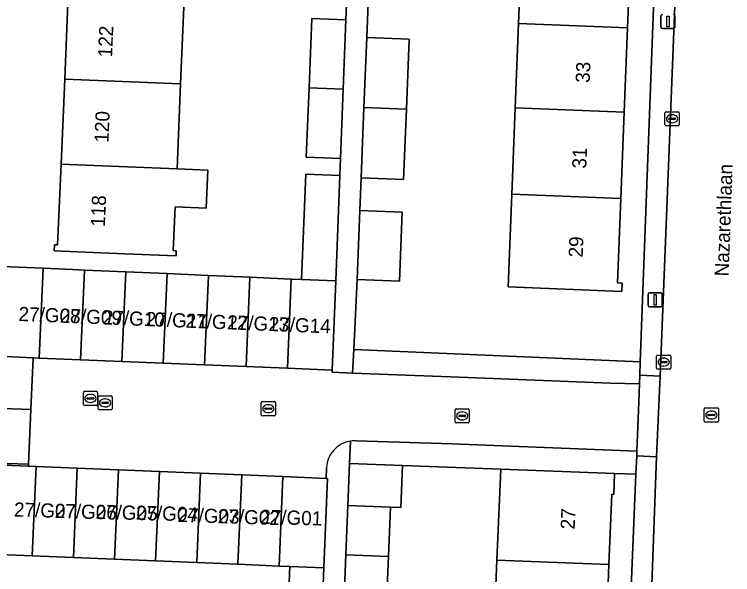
# Model space of a CAD drawing. Extents: x 161354 to 162026, y 386504 to 387460.
# Drawn here: x 161454.5 to 161505.3, y 387313.9 to 387353.5 of the extents above; entities that cross this region are included whole.
import ezdxf

# ---------------------------------------------------------------- set-up
doc = ezdxf.new("R2010")
doc.units = 0
for name, color, linetype in [('IMGEO_Erf', 7, 'Continuous'), ('IMGEO_Kolk', 7, 'Continuous'), ('IMGEO_Lichtmast', 7, 'Continuous'), ('IMGEO_Openbare_ruimte_label', 7, 'Continuous'), ('IMGEO_Pand', 7, 'Continuous'), ('IMGEO_Pand_nummerreeks', 7, 'Continuous'), ('IMGEO_Rijbaan_lokaal_open', 7, 'Continuous'), ('IMGEO_Rioolput', 7, 'Continuous'), ('IMGEO_Voetpad_open', 7, 'Continuous')]:
    doc.layers.add(name, color=color, linetype=linetype)

msp = doc.modelspace()

# ---------------------------------------------------------------- linework, layer by layer
at = {"layer": 'IMGEO_Erf'}
for points in [[(161479.478, 387354.331), (161479.382, 387351.907), (161482.38, 387351.788), (161482.183, 387346.822), (161481.986, 387341.858), (161478.988, 387341.977), (161478.897, 387339.661), (161481.894, 387339.542), (161481.701, 387334.668), (161478.704, 387334.787), (161478.46, 387329.827), (161498.714, 387328.954), (161500, 387363.41)], [(161498.072, 387358.868), (161497.821, 387352.583), (161497.583, 387346.613), (161497.339, 387340.512), (161497.101, 387334.546), (161497.442, 387334.532), (161497.419, 387333.947), (161489.37, 387334.268), (161489.632, 387340.821), (161489.876, 387346.922), (161490.114, 387352.891), (161490.365, 387359.176)], [(161453.573, 387335.71), (161456.498, 387335.582), (161458.569, 387335.492), (161459.424, 387335.455), (161462.349, 387335.327), (161465.274, 387335.199), (161468.2, 387335.072), (161471.125, 387334.944), (161474.051, 387334.817), (161474.773, 387334.785), (161475.065, 387342.244), (161477.483, 387342.146), (161477.53, 387343.346), (161475.112, 387343.441), (161475.304, 387348.337), (161475.496, 387353.233), (161477.915, 387353.138), (161478.001, 387355.333)], [(161466.483, 387354.617), (161466.227, 387348.614), (161465.972, 387342.612), (161468.145, 387342.524), (161468.03, 387339.827), (161465.832, 387339.921), (161465.7, 387336.824), (161465.916, 387336.815), (161465.901, 387336.451), (161462.284, 387336.605), (161457.288, 387336.817), (161457.306, 387337.241), (161457.531, 387337.231), (161457.774, 387342.945), (161458.029, 387348.947), (161458.285, 387354.95)], [(161451.637, 387325.727), (161455.634, 387325.588), (161455.79, 387329.244), (161453.296, 387329.353)], [(161453.093, 387321.69), (161455.463, 387321.592), (161455.468, 387321.718), (161451.502, 387321.855)], [(161488.347, 387309.015), (161488.591, 387314.933), (161488.868, 387321.367), (161481.919, 387321.628), (161481.801, 387318.661), (161481.051, 387318.691), (161480.912, 387315.2), (161480.717, 387310.314)], [(161497.171, 387291.265), (161498.419, 387321.01), (161496.91, 387321.066), (161496.854, 387319.589), (161496.703, 387319.595), (161496.51, 387314.625), (161496.28, 387308.706)], [(161473.671, 387307.859), (161473.94, 387314.493), (161473.186, 387314.524), (161470.277, 387314.645), (161467.367, 387314.765), (161464.458, 387314.885), (161461.549, 387315.006), (161458.64, 387315.126), (161455.731, 387315.247), (161449.389, 387315.509)]]:
    msp.add_lwpolyline(points, dxfattribs=at)
at = {"layer": 'IMGEO_Kolk'}
for p, q in [((161500.469, 387345.724), (161500.469, 387346.576)), ((161500.544, 387346.65), (161501.396, 387346.65)), ((161500.957, 387346.43), (161500.982, 387346.43)), ((161501.47, 387346.576), (161501.47, 387345.724)), ((161500.728, 387346.144), (161500.728, 387346.156)), ((161501.166, 387346.107), (161500.768, 387346.107)), ((161500.771, 387346.193), (161501.169, 387346.193)), ((161500.98, 387345.87), (161500.955, 387345.87)), ((161501.212, 387346.156), (161501.212, 387346.144)), ((161501.396, 387345.65), (161500.544, 387345.65)), ((161499.876, 387328.516), (161499.876, 387329.368)), ((161499.951, 387329.442), (161500.803, 387329.442)), ((161500.364, 387329.222), (161500.389, 387329.222)), ((161500.877, 387329.368), (161500.877, 387328.516)), ((161500.135, 387328.936), (161500.135, 387328.948)), ((161500.573, 387328.899), (161500.175, 387328.899)), ((161500.178, 387328.985), (161500.576, 387328.985)), ((161500.387, 387328.662), (161500.362, 387328.662)), ((161500.619, 387328.948), (161500.619, 387328.936)), ((161500.803, 387328.442), (161499.951, 387328.442)), ((161460.459, 387326.562), (161461.311, 387326.562)), ((161460.384, 387325.636), (161460.384, 387326.488)), ((161460.643, 387326.056), (161460.643, 387326.068)), ((161460.686, 387326.105), (161461.084, 387326.105)), ((161460.872, 387326.342), (161460.897, 387326.342)), ((161461.127, 387326.068), (161461.127, 387326.056)), ((161461.385, 387326.488), (161461.385, 387325.636)), ((161471.927, 387325.223), (161471.927, 387326.075)), ((161472.002, 387326.149), (161472.854, 387326.149)), ((161472.928, 387326.075), (161472.928, 387325.223)), ((161461.311, 387325.562), (161460.459, 387325.562)), ((161461.081, 387326.019), (161460.683, 387326.019)), ((161460.895, 387325.782), (161460.87, 387325.782)), ((161472.186, 387325.643), (161472.186, 387325.655)), ((161472.624, 387325.606), (161472.226, 387325.606)), ((161472.229, 387325.692), (161472.627, 387325.692)), ((161472.415, 387325.929), (161472.44, 387325.929)), ((161472.67, 387325.655), (161472.67, 387325.643)), ((161485.629, 387324.715), (161485.629, 387325.567)), ((161485.704, 387325.641), (161486.556, 387325.641)), ((161486.63, 387325.567), (161486.63, 387324.715)), ((161472.854, 387325.149), (161472.002, 387325.149)), ((161472.438, 387325.369), (161472.413, 387325.369)), ((161485.888, 387325.135), (161485.888, 387325.147)), ((161486.326, 387325.098), (161485.928, 387325.098)), ((161485.931, 387325.184), (161486.329, 387325.184)), ((161486.117, 387325.421), (161486.142, 387325.421)), ((161486.372, 387325.147), (161486.372, 387325.135)), ((161486.556, 387324.641), (161485.704, 387324.641)), ((161486.14, 387324.861), (161486.115, 387324.861))]:
    msp.add_line(p, q, dxfattribs=at)
for points in [[(161500.469, 387345.724), (161500.469, 387346.576)], [(161500.544, 387346.65), (161501.396, 387346.65)], [(161501.47, 387346.576), (161501.47, 387345.724)], [(161501.396, 387345.65), (161500.544, 387345.65)], [(161499.876, 387328.516), (161499.876, 387329.368)], [(161499.951, 387329.442), (161500.803, 387329.442)], [(161500.877, 387329.368), (161500.877, 387328.516)], [(161500.803, 387328.442), (161499.951, 387328.442)], [(161460.459, 387326.562), (161461.311, 387326.562)], [(161460.384, 387325.636), (161460.384, 387326.488)], [(161461.385, 387326.488), (161461.385, 387325.636)], [(161471.927, 387325.223), (161471.927, 387326.075)], [(161472.002, 387326.149), (161472.854, 387326.149)], [(161472.928, 387326.075), (161472.928, 387325.223)], [(161461.311, 387325.562), (161460.459, 387325.562)], [(161485.629, 387324.715), (161485.629, 387325.567)], [(161485.704, 387325.641), (161486.556, 387325.641)], [(161486.63, 387325.567), (161486.63, 387324.715)], [(161472.854, 387325.149), (161472.002, 387325.149)], [(161486.556, 387324.641), (161485.704, 387324.641)]]:
    msp.add_lwpolyline(points, dxfattribs=at)
for centre, radius, start, end in [((161500.546, 387346.574), 0.0765, 91.552, 178.448), ((161500.546, 387346.574), 0.0765, 91.552, 178.448), ((161501.394, 387346.574), 0.0765, 1.552, 88.448), ((161501.394, 387346.574), 0.0765, 1.552, 88.448), ((161500.768, 387346.153), 0.0403, 85.8775, 175.7526), ((161500.765, 387346.143), 0.0366, 178.938, 274.7102), ((161501.169, 387346.15), 0.043, 264.8664, 352.4533), ((161501.173, 387346.155), 0.0386, 1.7309, 96.639), ((161500.546, 387345.726), 0.0765, 181.552, 268.448), ((161500.546, 387345.726), 0.0765, 181.552, 268.448), ((161501.394, 387345.726), 0.0765, 271.552, 358.448), ((161501.394, 387345.726), 0.0765, 271.552, 358.448), ((161499.953, 387329.366), 0.0765, 91.552, 178.448), ((161499.953, 387329.366), 0.0765, 91.552, 178.448), ((161500.801, 387329.366), 0.0765, 1.552, 88.448), ((161500.801, 387329.366), 0.0765, 1.552, 88.448), ((161500.175, 387328.945), 0.0403, 85.8775, 175.7526), ((161500.172, 387328.935), 0.0366, 178.938, 274.7102), ((161500.576, 387328.942), 0.043, 264.8664, 352.4533), ((161500.58, 387328.947), 0.0386, 1.7309, 96.639), ((161499.953, 387328.518), 0.0765, 181.552, 268.448), ((161499.953, 387328.518), 0.0765, 181.552, 268.448), ((161500.801, 387328.518), 0.0765, 271.552, 358.448), ((161500.801, 387328.518), 0.0765, 271.552, 358.448), ((161460.461, 387326.486), 0.0765, 91.552, 178.448), ((161460.461, 387326.486), 0.0765, 91.552, 178.448), ((161461.309, 387326.486), 0.0765, 1.552, 88.448), ((161461.309, 387326.486), 0.0765, 1.552, 88.448), ((161460.683, 387326.065), 0.0403, 85.8775, 175.7526), ((161460.68, 387326.055), 0.0366, 178.938, 274.7102), ((161461.084, 387326.062), 0.043, 264.8664, 352.4533), ((161461.088, 387326.067), 0.0386, 1.7309, 96.639), ((161472.004, 387326.073), 0.0765, 91.552, 178.448), ((161472.004, 387326.073), 0.0765, 91.552, 178.448), ((161472.852, 387326.073), 0.0765, 1.552, 88.448), ((161472.852, 387326.073), 0.0765, 1.552, 88.448), ((161460.461, 387325.638), 0.0765, 181.552, 268.448), ((161460.461, 387325.638), 0.0765, 181.552, 268.448), ((161461.309, 387325.638), 0.0765, 271.552, 358.448), ((161461.309, 387325.638), 0.0765, 271.552, 358.448), ((161472.226, 387325.652), 0.0403, 85.8775, 175.7526), ((161472.223, 387325.642), 0.0366, 178.938, 274.7102), ((161472.627, 387325.649), 0.043, 264.8664, 352.4533), ((161472.631, 387325.654), 0.0386, 1.7309, 96.639), ((161485.706, 387325.565), 0.0765, 91.552, 178.448), ((161485.706, 387325.565), 0.0765, 91.552, 178.448), ((161486.554, 387325.565), 0.0765, 1.552, 88.448), ((161486.554, 387325.565), 0.0765, 1.552, 88.448), ((161472.004, 387325.225), 0.0765, 181.552, 268.448), ((161472.004, 387325.225), 0.0765, 181.552, 268.448), ((161472.852, 387325.225), 0.0765, 271.552, 358.448), ((161472.852, 387325.225), 0.0765, 271.552, 358.448), ((161485.928, 387325.144), 0.0403, 85.8775, 175.7526), ((161485.925, 387325.134), 0.0366, 178.938, 274.7102), ((161486.329, 387325.141), 0.043, 264.8664, 352.4533), ((161486.333, 387325.146), 0.0386, 1.7309, 96.639), ((161485.706, 387324.717), 0.0765, 181.552, 268.448), ((161485.706, 387324.717), 0.0765, 181.552, 268.448), ((161486.554, 387324.717), 0.0765, 271.552, 358.448), ((161486.554, 387324.717), 0.0765, 271.552, 358.448)]:
    msp.add_arc(centre, radius, start, end, dxfattribs=at)
for centre, major_axis, ratio, start_param, end_param in [((161500.956, 387346.15), (-0.387, 0.002), 0.722429, 4.712389, 7.853982), ((161500.981, 387346.15), (-0.39, 0.002), 0.717154, 1.570796, 4.712389), ((161500.363, 387328.942), (-0.387, 0.002), 0.722429, 4.712389, 7.853982), ((161500.388, 387328.942), (-0.39, 0.002), 0.717154, 1.570796, 4.712389), ((161460.871, 387326.062), (-0.387, 0.002), 0.722429, 4.712389, 7.853982), ((161460.896, 387326.062), (-0.39, 0.002), 0.717154, 1.570796, 4.712389), ((161472.414, 387325.649), (-0.387, 0.002), 0.722429, 4.712389, 7.853982), ((161472.439, 387325.649), (-0.39, 0.002), 0.717154, 1.570796, 4.712389), ((161486.116, 387325.141), (-0.387, 0.002), 0.722429, 4.712389, 7.853982), ((161486.141, 387325.141), (-0.39, 0.002), 0.717154, 1.570796, 4.712389)]:
    msp.add_ellipse(centre, major_axis=major_axis, ratio=ratio, start_param=start_param, end_param=end_param, dxfattribs=at)
at = {"layer": 'IMGEO_Lichtmast'}
for p, q in [((161500.184, 387352.633), (161500.184, 387353.433)), ((161500.184, 387353.433), (161500.184, 387352.633)), ((161501.174, 387353.433), (161501.174, 387352.633)), ((161501.174, 387352.633), (161501.174, 387353.433)), ((161501.074, 387352.533), (161500.284, 387352.533)), ((161500.284, 387352.533), (161501.074, 387352.533)), ((161499.285, 387332.942), (161499.285, 387333.742)), ((161499.285, 387333.742), (161499.285, 387332.942)), ((161499.385, 387333.842), (161500.175, 387333.842)), ((161500.175, 387333.842), (161499.385, 387333.842)), ((161500.275, 387333.742), (161500.275, 387332.942)), ((161500.275, 387332.942), (161500.275, 387333.742)), ((161500.175, 387332.842), (161499.385, 387332.842)), ((161499.385, 387332.842), (161500.175, 387332.842))]:
    msp.add_line(p, q, dxfattribs=at)
for points in [[(161500.604, 387353.408), (161500.754, 387353.408), (161500.754, 387352.658), (161500.604, 387352.658), (161500.604, 387353.408)], [(161499.705, 387333.717), (161499.855, 387333.717), (161499.855, 387332.967), (161499.705, 387332.967), (161499.705, 387333.717)]]:
    msp.add_lwpolyline(points, dxfattribs=at)
for centre, start, end in [((161500.284, 387353.433), 90, 180), ((161500.284, 387353.433), 90, 180), ((161501.074, 387353.433), 0, 90), ((161501.074, 387353.433), 360, 90), ((161500.284, 387352.633), 180, 270), ((161500.284, 387352.633), 180, 270), ((161501.074, 387352.633), 270, 0), ((161501.074, 387352.633), 270, 0), ((161499.385, 387333.742), 90, 180), ((161499.385, 387333.742), 90, 180), ((161500.175, 387333.742), 0, 90), ((161500.175, 387333.742), 360, 90), ((161499.385, 387332.942), 180, 270), ((161499.385, 387332.942), 180, 270), ((161500.175, 387332.942), 270, 0), ((161500.175, 387332.942), 270, 0)]:
    msp.add_arc(centre, 0.1, start, end, dxfattribs=at)
at = {"layer": 'IMGEO_Pand'}
for points in [[(161490.365, 387359.176), (161490.114, 387352.891), (161497.821, 387352.583), (161498.072, 387358.868)], [(161458.285, 387354.95), (161458.029, 387348.947), (161466.227, 387348.614), (161466.483, 387354.617)], [(161477.915, 387353.138), (161475.496, 387353.233), (161475.304, 387348.337), (161477.723, 387348.242)], [(161497.583, 387346.613), (161497.821, 387352.583), (161490.114, 387352.891), (161489.876, 387346.922)], [(161479.382, 387351.907), (161479.185, 387346.941), (161482.183, 387346.822), (161482.38, 387351.788)], [(161466.227, 387348.614), (161458.029, 387348.947), (161457.774, 387342.945), (161465.972, 387342.612)], [(161477.723, 387348.242), (161475.304, 387348.337), (161475.112, 387343.441), (161477.53, 387343.346)], [(161482.183, 387346.822), (161479.185, 387346.941), (161478.988, 387341.977), (161481.986, 387341.858)], [(161497.339, 387340.512), (161497.583, 387346.613), (161489.876, 387346.922), (161489.632, 387340.821)], [(161465.832, 387339.921), (161468.03, 387339.827), (161468.145, 387342.524), (161465.972, 387342.612), (161457.774, 387342.945), (161457.531, 387337.231), (161457.306, 387337.241), (161457.288, 387336.817), (161462.284, 387336.605), (161465.901, 387336.451), (161465.916, 387336.815), (161465.7, 387336.824)], [(161477.483, 387342.146), (161475.065, 387342.244), (161474.773, 387334.785), (161477.19, 387334.68)], [(161489.632, 387340.821), (161489.37, 387334.268), (161497.419, 387333.947), (161497.442, 387334.532), (161497.101, 387334.546), (161497.339, 387340.512)], [(161478.897, 387339.661), (161478.704, 387334.787), (161481.701, 387334.668), (161481.894, 387339.542)], [(161456.221, 387329.225), (161456.498, 387335.582), (161453.573, 387335.71), (161453.296, 387329.353), (161455.79, 387329.244)], [(161459.424, 387335.455), (161458.569, 387335.492), (161456.498, 387335.582), (161456.221, 387329.225), (161459.146, 387329.105)], [(161462.349, 387335.327), (161459.424, 387335.455), (161459.146, 387329.105), (161462.073, 387328.986)], [(161465.274, 387335.199), (161462.349, 387335.327), (161462.073, 387328.986), (161464.998, 387328.866)], [(161468.2, 387335.072), (161465.274, 387335.199), (161464.998, 387328.866), (161467.924, 387328.747)], [(161471.125, 387334.944), (161468.2, 387335.072), (161467.924, 387328.747), (161470.85, 387328.627)], [(161474.051, 387334.817), (161471.125, 387334.944), (161470.85, 387328.627), (161473.775, 387328.507)], [(161477.19, 387334.68), (161474.773, 387334.785), (161474.051, 387334.817), (161473.775, 387328.507), (161476.943, 387328.378)], [(161455.634, 387325.588), (161451.637, 387325.727), (161451.502, 387321.855), (161455.468, 387321.718)], [(161456.002, 387321.57), (161455.463, 387321.592), (161453.093, 387321.69), (161453.006, 387319.672), (161449.575, 387319.82), (161449.389, 387315.509), (161455.731, 387315.247)], [(161458.912, 387321.449), (161456.002, 387321.57), (161455.731, 387315.247), (161458.64, 387315.126)], [(161481.919, 387321.628), (161478.172, 387321.783), (161478.054, 387318.81), (161481.051, 387318.691), (161481.801, 387318.661)], [(161461.821, 387321.329), (161458.912, 387321.449), (161458.64, 387315.126), (161461.549, 387315.006)], [(161464.73, 387321.208), (161461.821, 387321.329), (161461.549, 387315.006), (161464.458, 387314.885)], [(161467.639, 387321.088), (161464.73, 387321.208), (161464.458, 387314.885), (161467.367, 387314.765)], [(161470.548, 387320.968), (161467.639, 387321.088), (161467.367, 387314.765), (161470.277, 387314.645)], [(161496.703, 387319.595), (161496.854, 387319.589), (161496.91, 387321.066), (161488.868, 387321.367), (161488.591, 387314.933), (161496.51, 387314.625)], [(161473.458, 387320.847), (161470.548, 387320.968), (161470.277, 387314.645), (161473.186, 387314.524)], [(161476.51, 387320.721), (161473.458, 387320.847), (161473.186, 387314.524), (161473.94, 387314.493), (161476.358, 387314.393), (161476.614, 387320.716)], [(161481.051, 387318.691), (161478.054, 387318.81), (161477.915, 387315.319), (161480.912, 387315.2)], [(161480.912, 387315.2), (161477.915, 387315.319), (161477.72, 387310.433), (161480.717, 387310.314)], [(161488.591, 387314.933), (161488.347, 387309.015), (161496.28, 387308.706), (161496.51, 387314.625)], [(161476.358, 387314.393), (161473.94, 387314.493), (161473.671, 387307.859), (161476.089, 387307.761)]]:
    msp.add_lwpolyline(points, close=True, dxfattribs=at)
at = {"layer": 'IMGEO_Rijbaan_lokaal_open'}
for points in [[(161502.454, 387386.874), (161500.117, 387327.957), (161499.877, 387322.239), (161499.07, 387300.302)], [(161498.568, 387324.92), (161498.656, 387327.384), (161498.657, 387327.408), (161496.596, 387327.461), (161486.557, 387327.847), (161478.378, 387328.168), (161476.937, 387328.224), (161476.943, 387328.378), (161473.775, 387328.507), (161470.85, 387328.627), (161467.924, 387328.747), (161464.998, 387328.866), (161462.073, 387328.986), (161459.146, 387329.105), (161456.221, 387329.225), (161455.79, 387329.244), (161455.634, 387325.588), (161455.468, 387321.718), (161455.463, 387321.592), (161456.002, 387321.57), (161458.912, 387321.449), (161461.821, 387321.329), (161464.73, 387321.208), (161467.639, 387321.088), (161470.548, 387320.968), (161473.458, 387320.847), (161476.51, 387320.721), (161476.54, 387321.475)], [(161478.661, 387323.383), (161485.419, 387323.168), (161498.487, 387322.651), (161498.568, 387324.92)]]:
    msp.add_lwpolyline(points, dxfattribs=at)
for centre, radius, start, end in [((161478.542, 387321.382), 2.005, 98.8236, 177.343), ((161478.545, 387321.312), 2.075, 86.7883, 98.5876)]:
    msp.add_arc(centre, radius, start, end, dxfattribs=at)
at = {"layer": 'IMGEO_Rioolput'}
for p, q in [((161459.347, 387325.951), (161459.347, 387326.803)), ((161459.422, 387326.877), (161460.274, 387326.877)), ((161459.835, 387326.657), (161459.86, 387326.657)), ((161460.348, 387326.803), (161460.348, 387325.951)), ((161459.606, 387326.371), (161459.606, 387326.383)), ((161460.044, 387326.334), (161459.646, 387326.334)), ((161459.649, 387326.42), (161460.047, 387326.42)), ((161459.858, 387326.097), (161459.833, 387326.097)), ((161460.09, 387326.383), (161460.09, 387326.371)), ((161460.274, 387325.877), (161459.422, 387325.877)), ((161503.246, 387324.776), (161503.246, 387325.628)), ((161503.321, 387325.702), (161504.173, 387325.702)), ((161504.247, 387325.628), (161504.247, 387324.776)), ((161503.505, 387325.196), (161503.505, 387325.208)), ((161503.943, 387325.159), (161503.545, 387325.159)), ((161503.548, 387325.245), (161503.946, 387325.245)), ((161503.734, 387325.482), (161503.759, 387325.482)), ((161503.989, 387325.208), (161503.989, 387325.196)), ((161504.173, 387324.702), (161503.321, 387324.702)), ((161503.757, 387324.922), (161503.732, 387324.922))]:
    msp.add_line(p, q, dxfattribs=at)
for points in [[(161459.347, 387325.951), (161459.347, 387326.803)], [(161459.422, 387326.877), (161460.274, 387326.877)], [(161460.348, 387326.803), (161460.348, 387325.951)], [(161460.274, 387325.877), (161459.422, 387325.877)], [(161503.246, 387324.776), (161503.246, 387325.628)], [(161503.321, 387325.702), (161504.173, 387325.702)], [(161504.247, 387325.628), (161504.247, 387324.776)], [(161504.173, 387324.702), (161503.321, 387324.702)]]:
    msp.add_lwpolyline(points, dxfattribs=at)
for centre, radius, start, end in [((161459.424, 387326.801), 0.0765, 91.552, 178.448), ((161459.424, 387326.801), 0.0765, 91.552, 178.448), ((161460.272, 387326.801), 0.0765, 1.552, 88.448), ((161460.272, 387326.801), 0.0765, 1.552, 88.448), ((161459.646, 387326.38), 0.0403, 85.8775, 175.7526), ((161459.643, 387326.37), 0.0366, 178.938, 274.7102), ((161460.047, 387326.377), 0.043, 264.8664, 352.4533), ((161460.051, 387326.382), 0.0386, 1.7309, 96.639), ((161459.424, 387325.953), 0.0765, 181.552, 268.448), ((161459.424, 387325.953), 0.0765, 181.552, 268.448), ((161460.272, 387325.953), 0.0765, 271.552, 358.448), ((161460.272, 387325.953), 0.0765, 271.552, 358.448), ((161503.323, 387325.626), 0.0765, 91.552, 178.448), ((161503.323, 387325.626), 0.0765, 91.552, 178.448), ((161504.171, 387325.626), 0.0765, 1.552, 88.448), ((161504.171, 387325.626), 0.0765, 1.552, 88.448), ((161503.545, 387325.205), 0.0403, 85.8775, 175.7526), ((161503.542, 387325.195), 0.0366, 178.938, 274.7102), ((161503.946, 387325.202), 0.043, 264.8664, 352.4533), ((161503.95, 387325.207), 0.0386, 1.7309, 96.639), ((161503.323, 387324.778), 0.0765, 181.552, 268.448), ((161503.323, 387324.778), 0.0765, 181.552, 268.448), ((161504.171, 387324.778), 0.0765, 271.552, 358.448), ((161504.171, 387324.778), 0.0765, 271.552, 358.448)]:
    msp.add_arc(centre, radius, start, end, dxfattribs=at)
for centre, major_axis, ratio, start_param, end_param in [((161459.834, 387326.377), (-0.387, 0.002), 0.722429, 4.712389, 7.853982), ((161459.859, 387326.377), (-0.39, 0.002), 0.717154, 1.570796, 4.712389), ((161503.733, 387325.202), (-0.387, 0.002), 0.722429, 4.712389, 7.853982), ((161503.758, 387325.202), (-0.39, 0.002), 0.717154, 1.570796, 4.712389)]:
    msp.add_ellipse(centre, major_axis=major_axis, ratio=ratio, start_param=start_param, end_param=end_param, dxfattribs=at)
at = {"layer": 'IMGEO_Voetpad_open'}
for points in [[(161500.844, 387386.024), (161500.745, 387383.379), (161500, 387363.41), (161498.714, 387328.954), (161498.68, 387328.024), (161500.117, 387327.957), (161502.454, 387386.874)], [(161478.001, 387355.333), (161477.915, 387353.138), (161477.723, 387348.242), (161477.53, 387343.346), (161477.483, 387342.146), (161477.19, 387334.68), (161476.943, 387328.378), (161476.937, 387328.224), (161478.378, 387328.168), (161478.46, 387329.827), (161478.704, 387334.787), (161478.897, 387339.661), (161478.988, 387341.977), (161479.185, 387346.941), (161479.382, 387351.907), (161479.478, 387354.331)], [(161476.497, 387279.767), (161476.695, 387284.733), (161476.893, 387289.689), (161476.988, 387292.075), (161477.187, 387297.061), (161477.385, 387302.039), (161477.482, 387304.459), (161477.676, 387309.345), (161477.72, 387310.433), (161477.915, 387315.319), (161478.054, 387318.81), (161478.172, 387321.783), (161478.235, 387323.363)], [(161478.235, 387323.363), (161478.172, 387321.783), (161481.919, 387321.628), (161488.868, 387321.367), (161496.91, 387321.066), (161498.419, 387321.01), (161498.474, 387322.304)], [(161498.474, 387322.304), (161498.48, 387322.455), (161498.487, 387322.651), (161485.419, 387323.168), (161478.661, 387323.383)], [(161499.07, 387300.302), (161499.877, 387322.239), (161498.474, 387322.304), (161498.419, 387321.01), (161497.171, 387291.265)], [(161476.54, 387321.475), (161476.51, 387320.721), (161476.614, 387320.716), (161476.358, 387314.393), (161476.089, 387307.761)]]:
    msp.add_lwpolyline(points, dxfattribs=at)
for points in [[(161498.714, 387328.954), (161478.46, 387329.827), (161478.378, 387328.168), (161486.557, 387327.847), (161496.596, 387327.461), (161498.657, 387327.408), (161498.68, 387328.024)], [(161500.117, 387327.957), (161498.68, 387328.024), (161498.657, 387327.408), (161498.656, 387327.384), (161498.568, 387324.92), (161498.487, 387322.651), (161498.48, 387322.455), (161498.474, 387322.304), (161499.877, 387322.239)]]:
    msp.add_lwpolyline(points, close=True, dxfattribs=at)
for centre, radius, start, end in [((161478.542, 387321.382), 2.005, 98.8236, 177.343), ((161478.545, 387321.312), 2.075, 86.7883, 98.5876)]:
    msp.add_arc(centre, radius, start, end, dxfattribs=at)

# ---------------------------------------------------------------- texts
at = {"layer": 'IMGEO_Openbare_ruimte_label'}
msp.add_text('Nazarethlaan', height=1, rotation=87.9362, dxfattribs=at).set_placement((161504.968, 387334.989))
at = {"layer": 'IMGEO_Pand_nummerreeks'}
for s, rotation, p in [('122', 87.5637, (161461.377, 387350.478)), ('33', 87.713, (161495.144, 387348.675)), ('120', 87.5651, (161461.122, 387344.445)), ('31', 87.713, (161494.902, 387342.612)), ('118', 87.5651, (161460.868, 387338.496)), ('29', 87.713, (161494.65, 387336.323)), ('27/G08', 357.7024, (161454.748, 387331.856)), ('27/G09', 357.7024, (161457.674, 387331.738)), ('27/G10', 357.7024, (161460.705, 387331.616)), ('27/G11', 357.7024, (161463.745, 387331.495)), ('27/G12', 357.7024, (161466.561, 387331.381)), ('27/G13', 357.7024, (161469.501, 387331.264)), ('27/G14', 357.7024, (161472.434, 387331.146)), ('27/G07', 358.2926, (161454.432, 387318.024)), ('27/G06', 358.2926, (161457.315, 387317.929)), ('27/G05', 358.2926, (161460.198, 387317.866)), ('27/G04', 358.2926, (161463.05, 387317.802)), ('27/G03', 358.2926, (161465.995, 387317.643)), ('27/G02', 358.2926, (161468.842, 387317.549)), ('27/G01', 358.2926, (161471.841, 387317.514)), ('27', 87.7714, (161494.084, 387317.096))]:
    msp.add_text(s, height=1, rotation=rotation, dxfattribs=at).set_placement(p)

doc.saveas('drawing.dxf')
